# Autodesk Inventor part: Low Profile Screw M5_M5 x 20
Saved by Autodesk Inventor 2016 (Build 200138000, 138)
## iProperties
Created: 2016-03
Part Number: Low Profile Screw M5_M5 x 20
Material: Generic
Document SubType Name: Modeling
Designer: bongo_000
Density: 1 g/cm^3
Appearance: Default
Author: bongo_000
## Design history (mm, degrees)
feature "CUT-EXTRUDE2"
body "Solid1"
